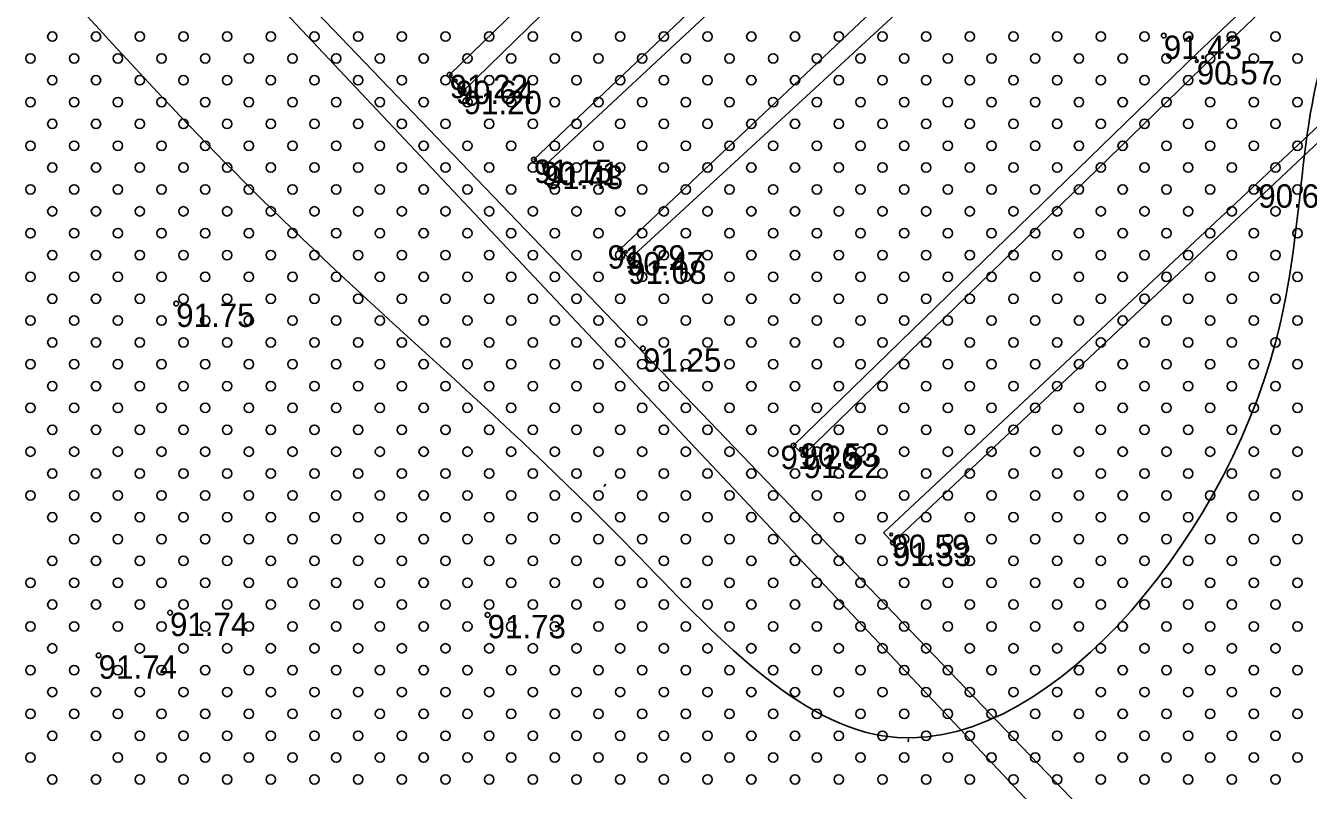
# Model space of a CAD drawing. Extents: x 316000 to 728450, y 314368 to 726000.
# Drawn here: x 725766.2 to 725971.8, y 315036.8 to 315159.2 of the extents above; entities that cross this region are included whole.
import ezdxf

# ---------------------------------------------------------------- set-up
doc = ezdxf.new("R2010")
doc.units = 0
for name, color, linetype in [('HIDG_ELEM_####_####_#', 7, 'Continuous'), ('HIDG_GRAV_####_####_#', 7, 'Continuous'), ('RELJ_AATZ_####_TKST_#', 7, 'Continuous'), ('RELJ_ELEM_####_####_#', 7, 'Continuous'), ('RELJ_HORZ_PAMT_####_#', 7, 'Continuous'), ('RELJ_NOGA_####_####_#', 7, 'Continuous'), ('TERT_ELEM_####_####_#', 7, 'Continuous'), ('TERT_KONT_####_####_#', 7, 'Continuous')]:
    doc.layers.add(name, color=color, linetype=linetype)

msp = doc.modelspace()

# ---------------------------------------------------------------- linework, layer by layer
at = {"layer": 'HIDG_ELEM_####_####_#'}
for centre in [(725953.87, 315153.57), (725835.14, 315150.43), (725848.81, 315137.44), (725963.77, 315133.08), (725862.38, 315123), (725890.5, 315091.43), (725904.91, 315077.72)]:
    msp.add_circle(centre, 0.225, dxfattribs=at)
at = {"layer": 'HIDG_GRAV_####_####_#'}
for points in [[(725550.64, 315437.37), (725654.91, 315324.09), (725793.17, 315176.93), (726030.02, 314925.45), (726035.1, 314929.94), (725796.17, 315178.83)], [(726013.86, 315323.76), (726014.55, 315322.37), (725916.94, 315227.27), (725836.4, 315148.81), (725834.15, 315151.37), (725916.39, 315231.21), (726013.86, 315323.76)], [(726026.72, 315310.03), (726028.38, 315308.12), (725929.27, 315211.22), (725849.42, 315136.82), (725847.67, 315137.8), (725927.82, 315213.86), (726026.72, 315310.03)], [(726041.22, 315294.28), (726042.74, 315292.12), (725933.2, 315186.57), (725862.99, 315121.84), (725861.5, 315123.44), (725931.43, 315189.54), (726041.22, 315294.28)], [(726067.39, 315262.47), (726068.58, 315261.15), (725954.8, 315152.62), (725890.85, 315090.51), (725889.28, 315091.99), (725953.78, 315154.65), (726067.39, 315262.47)], [(726082.26, 315247.75), (726083.77, 315246.23), (726040.2, 315203.48), (725905.19, 315076.43), (725903.68, 315078.01), (726039.2, 315204.79), (726082.26, 315247.75)]]:
    msp.add_lwpolyline(points, dxfattribs=at)
at = {"layer": 'RELJ_ELEM_####_####_#'}
for centre in [(725948.58, 315157.65), (725834.15, 315151.37), (725836.4, 315148.81), (725847.67, 315137.8), (725849.42, 315136.82), (725861.5, 315123.44), (725862.99, 315121.84), (725790.35, 315114.73), (725865.14, 315107.54), (725889.28, 315091.99), (725890.85, 315090.51), (725905.19, 315076.43), (725789.36, 315065.21), (725840.24, 315064.86), (725777.92, 315058.37)]:
    msp.add_circle(centre, 0.375, dxfattribs=at)
at = {"layer": 'RELJ_HORZ_PAMT_####_#'}
for p, q in [((725859.18, 315085.78), (725858.85, 315085.4)), ((725907.67, 315045.01), (725907.62, 315044.51))]:
    msp.add_line(p, q, dxfattribs=at)
for points in [[(726116.34, 315699.09), (726105.94, 315702.69), (726040.13, 315715), (725990.82, 315710.42), (725942.03, 315708.25), (725920.28, 315706.77), (725880.37, 315714.51), (725859.05, 315708.68), (725859.05, 315672.66), (725851.26, 315613.97), (725853.47, 315568.9), (725841, 315555.79), (725885.56, 315509.63), (725935.94, 315461.49), (725983.42, 315406.25), (726032.86, 315360.51), (726082.85, 315311.19), (726122.23, 315248.76), (726137.05, 315229.29), (726180.19, 315183.1), (726194.52, 315168.27), (726211.91, 315146.93), (726212.51, 315143.16)], [(726081.57, 315247.05), (726057.5, 315241.5), (726036.5, 315213.5), (725977, 315161), (725966.5, 315108.5), (725903.5, 315045.5), (725862.12, 315076.6), (725805.5, 315130), (725759.7, 315178.88), (725709.89, 315228.8), (725646.99, 315287.19), (725634.68, 315314.96), (725629.04, 315327.48), (725557.35, 315340.26), (725478.3, 315344.16)]]:
    msp.add_spline(points, degree=3, dxfattribs=at)
at = {"layer": 'RELJ_NOGA_####_####_#'}
for points in [[(726259.12, 315084.51), (726262.72, 315089.26), (726261.56, 315090.84), (726260.2, 315092.42), (726257.29, 315095.53), (726218.91, 315136.38), (726180.31, 315176.84), (726128.67, 315229.97), (726063.7, 315298.11), (725999.9, 315366.09), (725937.21, 315432.09), (725876.35, 315495.23), (725810.58, 315563.08), (725744.7, 315632.91)], [(725740.86, 315626.98), (725805.54, 315558.12), (725870.39, 315491.15), (725932.8, 315426.8), (725994.98, 315360.84), (726059.66, 315292.12), (726075.75, 315275.46), (726092.08, 315259.04), (726108.47, 315242.67), (726124.69, 315226.14), (726193.27, 315154.03), (726250.06, 315092.6), (726256.32, 315085.83), (726258.82, 315084.29), (726259.12, 315084.51)]]:
    msp.add_spline(points, degree=3, dxfattribs=at)
at = {"layer": 'TERT_ELEM_####_####_#'}
for centre in [(725770.5, 315157.5), (725777.5, 315157.5), (725784.5, 315157.5), (725791.5, 315157.5), (725798.5, 315157.5), (725805.5, 315157.5), (725812.5, 315157.5), (725819.5, 315157.5), (725826.5, 315157.5), (725833.5, 315157.5), (725840.5, 315157.5), (725847.5, 315157.5), (725854.5, 315157.5), (725861.5, 315157.5), (725868.5, 315157.5), (725875.5, 315157.5), (725882.5, 315157.5), (725889.5, 315157.5), (725896.5, 315157.5), (725903.5, 315157.5), (725910.5, 315157.5), (725917.5, 315157.5), (725924.5, 315157.5), (725931.5, 315157.5), (725938.5, 315157.5), (725945.5, 315157.5), (725952.5, 315157.5), (725959.5, 315157.5), (725966.5, 315157.5), (725767, 315154), (725774, 315154), (725781, 315154), (725788, 315154), (725795, 315154), (725802, 315154), (725809, 315154), (725816, 315154), (725823, 315154), (725830, 315154), (725837, 315154), (725844, 315154), (725851, 315154), (725858, 315154), (725865, 315154), (725872, 315154), (725879, 315154), (725886, 315154), (725893, 315154), (725900, 315154), (725907, 315154), (725914, 315154), (725921, 315154), (725928, 315154), (725935, 315154), (725942, 315154), (725949, 315154), (725956, 315154), (725963, 315154), (725970, 315154), (725770.5, 315150.5), (725777.5, 315150.5), (725784.5, 315150.5), (725791.5, 315150.5), (725798.5, 315150.5), (725805.5, 315150.5), (725812.5, 315150.5), (725819.5, 315150.5), (725826.5, 315150.5), (725833.5, 315150.5), (725840.5, 315150.5), (725847.5, 315150.5), (725854.5, 315150.5), (725861.5, 315150.5), (725868.5, 315150.5), (725875.5, 315150.5), (725882.5, 315150.5), (725889.5, 315150.5), (725896.5, 315150.5), (725903.5, 315150.5), (725910.5, 315150.5), (725917.5, 315150.5), (725924.5, 315150.5), (725931.5, 315150.5), (725938.5, 315150.5), (725945.5, 315150.5), (725952.5, 315150.5), (725959.5, 315150.5), (725966.5, 315150.5), (725767, 315147), (725774, 315147), (725781, 315147), (725788, 315147), (725795, 315147), (725802, 315147), (725809, 315147), (725816, 315147), (725823, 315147), (725830, 315147), (725837, 315147), (725844, 315147), (725851, 315147), (725858, 315147), (725865, 315147), (725872, 315147), (725879, 315147), (725886, 315147), (725893, 315147), (725900, 315147), (725907, 315147), (725914, 315147), (725921, 315147), (725928, 315147), (725935, 315147), (725942, 315147), (725949, 315147), (725956, 315147), (725963, 315147), (725970, 315147), (725770.5, 315143.5), (725777.5, 315143.5), (725784.5, 315143.5), (725791.5, 315143.5), (725798.5, 315143.5), (725805.5, 315143.5), (725812.5, 315143.5), (725819.5, 315143.5), (725826.5, 315143.5), (725833.5, 315143.5), (725840.5, 315143.5), (725847.5, 315143.5), (725854.5, 315143.5), (725861.5, 315143.5), (725868.5, 315143.5), (725875.5, 315143.5), (725882.5, 315143.5), (725889.5, 315143.5), (725896.5, 315143.5), (725903.5, 315143.5), (725910.5, 315143.5), (725917.5, 315143.5), (725924.5, 315143.5), (725931.5, 315143.5), (725938.5, 315143.5), (725945.5, 315143.5), (725952.5, 315143.5), (725959.5, 315143.5), (725966.5, 315143.5), (725767, 315140), (725774, 315140), (725781, 315140), (725788, 315140), (725795, 315140), (725802, 315140), (725809, 315140), (725816, 315140), (725823, 315140), (725830, 315140), (725837, 315140), (725844, 315140), (725851, 315140), (725858, 315140), (725865, 315140), (725872, 315140), (725879, 315140), (725886, 315140), (725893, 315140), (725900, 315140), (725907, 315140), (725914, 315140), (725921, 315140), (725928, 315140), (725935, 315140), (725942, 315140), (725949, 315140), (725956, 315140), (725963, 315140), (725970, 315140), (725770.5, 315136.5), (725777.5, 315136.5), (725784.5, 315136.5), (725791.5, 315136.5), (725798.5, 315136.5), (725805.5, 315136.5), (725812.5, 315136.5), (725819.5, 315136.5), (725826.5, 315136.5), (725833.5, 315136.5), (725840.5, 315136.5), (725847.5, 315136.5), (725854.5, 315136.5), (725861.5, 315136.5), (725868.5, 315136.5), (725875.5, 315136.5), (725882.5, 315136.5), (725889.5, 315136.5), (725896.5, 315136.5), (725903.5, 315136.5), (725910.5, 315136.5), (725917.5, 315136.5), (725924.5, 315136.5), (725931.5, 315136.5), (725938.5, 315136.5), (725945.5, 315136.5), (725952.5, 315136.5), (725959.5, 315136.5), (725966.5, 315136.5), (725767, 315133), (725774, 315133), (725781, 315133), (725788, 315133), (725795, 315133), (725802, 315133), (725809, 315133), (725816, 315133), (725823, 315133), (725830, 315133), (725837, 315133), (725844, 315133), (725851, 315133), (725858, 315133), (725865, 315133), (725872, 315133), (725879, 315133), (725886, 315133), (725893, 315133), (725900, 315133), (725907, 315133), (725914, 315133), (725921, 315133), (725928, 315133), (725935, 315133), (725942, 315133), (725949, 315133), (725956, 315133), (725963, 315133), (725970, 315133), (725770.5, 315129.5), (725777.5, 315129.5), (725784.5, 315129.5), (725791.5, 315129.5), (725798.5, 315129.5), (725805.5, 315129.5), (725812.5, 315129.5), (725819.5, 315129.5), (725826.5, 315129.5), (725833.5, 315129.5), (725840.5, 315129.5), (725847.5, 315129.5), (725854.5, 315129.5), (725861.5, 315129.5), (725868.5, 315129.5), (725875.5, 315129.5), (725882.5, 315129.5), (725889.5, 315129.5), (725896.5, 315129.5), (725903.5, 315129.5), (725910.5, 315129.5), (725917.5, 315129.5), (725924.5, 315129.5), (725931.5, 315129.5), (725938.5, 315129.5), (725945.5, 315129.5), (725952.5, 315129.5), (725959.5, 315129.5), (725966.5, 315129.5), (725767, 315126), (725774, 315126), (725781, 315126), (725788, 315126), (725795, 315126), (725802, 315126), (725809, 315126), (725816, 315126), (725823, 315126), (725830, 315126), (725837, 315126), (725844, 315126), (725851, 315126), (725858, 315126), (725865, 315126), (725872, 315126), (725879, 315126), (725886, 315126), (725893, 315126), (725900, 315126), (725907, 315126), (725914, 315126), (725921, 315126), (725928, 315126), (725935, 315126), (725942, 315126), (725949, 315126), (725956, 315126), (725963, 315126), (725970, 315126), (725770.5, 315122.5), (725777.5, 315122.5), (725784.5, 315122.5), (725791.5, 315122.5), (725798.5, 315122.5), (725805.5, 315122.5), (725812.5, 315122.5), (725819.5, 315122.5), (725826.5, 315122.5), (725833.5, 315122.5), (725840.5, 315122.5), (725847.5, 315122.5), (725854.5, 315122.5), (725861.5, 315122.5), (725868.5, 315122.5), (725875.5, 315122.5), (725882.5, 315122.5), (725889.5, 315122.5), (725896.5, 315122.5), (725903.5, 315122.5), (725910.5, 315122.5), (725917.5, 315122.5), (725924.5, 315122.5), (725931.5, 315122.5), (725938.5, 315122.5), (725945.5, 315122.5), (725952.5, 315122.5), (725959.5, 315122.5), (725966.5, 315122.5), (725767, 315119), (725774, 315119), (725781, 315119), (725788, 315119), (725795, 315119), (725802, 315119), (725809, 315119), (725816, 315119), (725823, 315119), (725830, 315119), (725837, 315119), (725844, 315119), (725851, 315119), (725858, 315119), (725865, 315119), (725872, 315119), (725879, 315119), (725886, 315119), (725893, 315119), (725900, 315119), (725907, 315119), (725914, 315119), (725921, 315119), (725928, 315119), (725935, 315119), (725942, 315119), (725949, 315119), (725956, 315119), (725963, 315119), (725970, 315119), (725770.5, 315115.5), (725777.5, 315115.5), (725784.5, 315115.5), (725791.5, 315115.5), (725798.5, 315115.5), (725805.5, 315115.5), (725812.5, 315115.5), (725819.5, 315115.5), (725826.5, 315115.5), (725833.5, 315115.5), (725840.5, 315115.5), (725847.5, 315115.5), (725854.5, 315115.5), (725861.5, 315115.5), (725868.5, 315115.5), (725875.5, 315115.5), (725882.5, 315115.5), (725889.5, 315115.5), (725896.5, 315115.5), (725903.5, 315115.5), (725910.5, 315115.5), (725917.5, 315115.5), (725924.5, 315115.5), (725931.5, 315115.5), (725938.5, 315115.5), (725945.5, 315115.5), (725952.5, 315115.5), (725959.5, 315115.5), (725966.5, 315115.5), (725767, 315112), (725774, 315112), (725781, 315112), (725788, 315112), (725795, 315112), (725802, 315112), (725809, 315112), (725816, 315112), (725823, 315112), (725830, 315112), (725837, 315112), (725844, 315112), (725851, 315112), (725858, 315112), (725865, 315112), (725872, 315112), (725879, 315112), (725886, 315112), (725893, 315112), (725900, 315112), (725907, 315112), (725914, 315112), (725921, 315112), (725928, 315112), (725935, 315112), (725942, 315112), (725949, 315112), (725956, 315112), (725963, 315112), (725970, 315112), (725770.5, 315108.5), (725777.5, 315108.5), (725784.5, 315108.5), (725791.5, 315108.5), (725798.5, 315108.5), (725805.5, 315108.5), (725812.5, 315108.5), (725819.5, 315108.5), (725826.5, 315108.5), (725833.5, 315108.5), (725840.5, 315108.5), (725847.5, 315108.5), (725854.5, 315108.5), (725861.5, 315108.5), (725868.5, 315108.5), (725875.5, 315108.5), (725882.5, 315108.5), (725889.5, 315108.5), (725896.5, 315108.5), (725903.5, 315108.5), (725910.5, 315108.5), (725917.5, 315108.5), (725924.5, 315108.5), (725931.5, 315108.5), (725938.5, 315108.5), (725945.5, 315108.5), (725952.5, 315108.5), (725959.5, 315108.5), (725966.5, 315108.5), (725767, 315105), (725774, 315105), (725781, 315105), (725788, 315105), (725795, 315105), (725802, 315105), (725809, 315105), (725816, 315105), (725823, 315105), (725830, 315105), (725837, 315105), (725844, 315105), (725851, 315105), (725858, 315105), (725865, 315105), (725872, 315105), (725879, 315105), (725886, 315105), (725893, 315105), (725900, 315105), (725907, 315105), (725914, 315105), (725921, 315105), (725928, 315105), (725935, 315105), (725942, 315105), (725949, 315105), (725956, 315105), (725963, 315105), (725970, 315105), (725770.5, 315101.5), (725777.5, 315101.5), (725784.5, 315101.5), (725791.5, 315101.5), (725798.5, 315101.5), (725805.5, 315101.5), (725812.5, 315101.5), (725819.5, 315101.5), (725826.5, 315101.5), (725833.5, 315101.5), (725840.5, 315101.5), (725847.5, 315101.5), (725854.5, 315101.5), (725861.5, 315101.5), (725868.5, 315101.5), (725875.5, 315101.5), (725882.5, 315101.5), (725889.5, 315101.5), (725896.5, 315101.5), (725903.5, 315101.5), (725910.5, 315101.5), (725917.5, 315101.5), (725924.5, 315101.5), (725931.5, 315101.5), (725938.5, 315101.5), (725945.5, 315101.5), (725952.5, 315101.5), (725959.5, 315101.5), (725966.5, 315101.5), (725767, 315098), (725774, 315098), (725781, 315098), (725788, 315098), (725795, 315098), (725802, 315098), (725809, 315098), (725816, 315098), (725823, 315098), (725830, 315098), (725837, 315098), (725844, 315098), (725851, 315098), (725858, 315098), (725865, 315098), (725872, 315098), (725879, 315098), (725886, 315098), (725893, 315098), (725900, 315098), (725907, 315098), (725914, 315098), (725921, 315098), (725928, 315098), (725935, 315098), (725942, 315098), (725949, 315098), (725956, 315098), (725963, 315098), (725970, 315098), (725770.5, 315094.5), (725777.5, 315094.5), (725784.5, 315094.5), (725791.5, 315094.5), (725798.5, 315094.5), (725805.5, 315094.5), (725812.5, 315094.5), (725819.5, 315094.5), (725826.5, 315094.5), (725833.5, 315094.5), (725840.5, 315094.5), (725847.5, 315094.5), (725854.5, 315094.5), (725861.5, 315094.5), (725868.5, 315094.5), (725875.5, 315094.5), (725882.5, 315094.5), (725889.5, 315094.5), (725896.5, 315094.5), (725903.5, 315094.5), (725910.5, 315094.5), (725917.5, 315094.5), (725924.5, 315094.5), (725931.5, 315094.5), (725938.5, 315094.5), (725945.5, 315094.5), (725952.5, 315094.5), (725959.5, 315094.5), (725966.5, 315094.5), (725767, 315091), (725774, 315091), (725781, 315091), (725788, 315091), (725795, 315091), (725802, 315091), (725809, 315091), (725816, 315091), (725823, 315091), (725830, 315091), (725837, 315091), (725844, 315091), (725851, 315091), (725858, 315091), (725865, 315091), (725872, 315091), (725879, 315091), (725886, 315091), (725893, 315091), (725900, 315091), (725907, 315091), (725914, 315091), (725921, 315091), (725928, 315091), (725935, 315091), (725942, 315091), (725949, 315091), (725956, 315091), (725963, 315091), (725970, 315091), (725770.5, 315087.5), (725777.5, 315087.5), (725784.5, 315087.5), (725791.5, 315087.5), (725798.5, 315087.5), (725805.5, 315087.5), (725812.5, 315087.5), (725819.5, 315087.5), (725826.5, 315087.5), (725833.5, 315087.5), (725840.5, 315087.5), (725847.5, 315087.5), (725854.5, 315087.5), (725861.5, 315087.5), (725868.5, 315087.5), (725875.5, 315087.5), (725882.5, 315087.5), (725889.5, 315087.5), (725896.5, 315087.5), (725903.5, 315087.5), (725910.5, 315087.5), (725917.5, 315087.5), (725924.5, 315087.5), (725931.5, 315087.5), (725938.5, 315087.5), (725945.5, 315087.5), (725952.5, 315087.5), (725959.5, 315087.5), (725966.5, 315087.5), (725767, 315084), (725774, 315084), (725781, 315084), (725788, 315084), (725795, 315084), (725802, 315084), (725809, 315084), (725816, 315084), (725823, 315084), (725830, 315084), (725837, 315084), (725844, 315084), (725851, 315084), (725858, 315084), (725865, 315084), (725872, 315084), (725879, 315084), (725886, 315084), (725893, 315084), (725900, 315084), (725907, 315084), (725914, 315084), (725921, 315084), (725928, 315084), (725935, 315084), (725942, 315084), (725949, 315084), (725956, 315084), (725963, 315084), (725970, 315084), (725770.5, 315080.5), (725777.5, 315080.5), (725784.5, 315080.5), (725791.5, 315080.5), (725798.5, 315080.5), (725805.5, 315080.5), (725812.5, 315080.5), (725819.5, 315080.5), (725826.5, 315080.5), (725833.5, 315080.5), (725840.5, 315080.5), (725847.5, 315080.5), (725854.5, 315080.5), (725861.5, 315080.5), (725868.5, 315080.5), (725875.5, 315080.5), (725882.5, 315080.5), (725889.5, 315080.5), (725896.5, 315080.5), (725903.5, 315080.5), (725910.5, 315080.5), (725917.5, 315080.5), (725924.5, 315080.5), (725931.5, 315080.5), (725938.5, 315080.5), (725945.5, 315080.5), (725952.5, 315080.5), (725959.5, 315080.5), (725966.5, 315080.5), (725774, 315077), (725781, 315077), (725788, 315077), (725795, 315077), (725802, 315077), (725809, 315077), (725816, 315077), (725823, 315077), (725830, 315077), (725837, 315077), (725844, 315077), (725851, 315077), (725858, 315077), (725865, 315077), (725872, 315077), (725879, 315077), (725886, 315077), (725893, 315077), (725900, 315077), (725907, 315077), (725914, 315077), (725921, 315077), (725928, 315077), (725935, 315077), (725942, 315077), (725949, 315077), (725956, 315077), (725963, 315077), (725970, 315077), (725770.5, 315073.5), (725777.5, 315073.5), (725784.5, 315073.5), (725791.5, 315073.5), (725798.5, 315073.5), (725805.5, 315073.5), (725812.5, 315073.5), (725819.5, 315073.5), (725826.5, 315073.5), (725833.5, 315073.5), (725840.5, 315073.5), (725847.5, 315073.5), (725854.5, 315073.5), (725861.5, 315073.5), (725868.5, 315073.5), (725875.5, 315073.5), (725882.5, 315073.5), (725889.5, 315073.5), (725896.5, 315073.5), (725903.5, 315073.5), (725910.5, 315073.5), (725917.5, 315073.5), (725924.5, 315073.5), (725931.5, 315073.5), (725938.5, 315073.5), (725945.5, 315073.5), (725952.5, 315073.5), (725959.5, 315073.5), (725966.5, 315073.5), (725767, 315070), (725774, 315070), (725781, 315070), (725788, 315070), (725795, 315070), (725802, 315070), (725809, 315070), (725816, 315070), (725823, 315070), (725830, 315070), (725837, 315070), (725844, 315070), (725851, 315070), (725858, 315070), (725865, 315070), (725872, 315070), (725879, 315070), (725886, 315070), (725893, 315070), (725900, 315070), (725907, 315070), (725914, 315070), (725921, 315070), (725928, 315070), (725935, 315070), (725942, 315070), (725949, 315070), (725956, 315070), (725963, 315070), (725970, 315070), (725770.5, 315066.5), (725777.5, 315066.5), (725784.5, 315066.5), (725791.5, 315066.5), (725798.5, 315066.5), (725805.5, 315066.5), (725812.5, 315066.5), (725819.5, 315066.5), (725826.5, 315066.5), (725833.5, 315066.5), (725840.5, 315066.5), (725847.5, 315066.5), (725854.5, 315066.5), (725861.5, 315066.5), (725868.5, 315066.5), (725875.5, 315066.5), (725882.5, 315066.5), (725889.5, 315066.5), (725896.5, 315066.5), (725903.5, 315066.5), (725910.5, 315066.5), (725917.5, 315066.5), (725924.5, 315066.5), (725931.5, 315066.5), (725938.5, 315066.5), (725945.5, 315066.5), (725952.5, 315066.5), (725959.5, 315066.5), (725966.5, 315066.5), (725767, 315063), (725774, 315063), (725781, 315063), (725788, 315063), (725795, 315063), (725802, 315063), (725809, 315063), (725816, 315063), (725823, 315063), (725830, 315063), (725837, 315063), (725844, 315063), (725851, 315063), (725858, 315063), (725865, 315063), (725872, 315063), (725879, 315063), (725886, 315063), (725893, 315063), (725900, 315063), (725907, 315063), (725914, 315063), (725921, 315063), (725928, 315063), (725935, 315063), (725942, 315063), (725949, 315063), (725956, 315063), (725963, 315063), (725970, 315063), (725770.5, 315059.5), (725784.5, 315059.5), (725791.5, 315059.5), (725798.5, 315059.5), (725805.5, 315059.5), (725812.5, 315059.5), (725819.5, 315059.5), (725826.5, 315059.5), (725833.5, 315059.5), (725840.5, 315059.5), (725847.5, 315059.5), (725854.5, 315059.5), (725861.5, 315059.5), (725868.5, 315059.5), (725875.5, 315059.5), (725882.5, 315059.5), (725889.5, 315059.5), (725896.5, 315059.5), (725903.5, 315059.5), (725910.5, 315059.5), (725917.5, 315059.5), (725924.5, 315059.5), (725931.5, 315059.5), (725938.5, 315059.5), (725945.5, 315059.5), (725952.5, 315059.5), (725959.5, 315059.5), (725966.5, 315059.5), (725767, 315056), (725774, 315056), (725781, 315056), (725788, 315056), (725795, 315056), (725802, 315056), (725809, 315056), (725816, 315056), (725823, 315056), (725830, 315056), (725837, 315056), (725844, 315056), (725851, 315056), (725858, 315056), (725865, 315056), (725872, 315056), (725879, 315056), (725886, 315056), (725893, 315056), (725900, 315056), (725907, 315056), (725914, 315056), (725921, 315056), (725928, 315056), (725935, 315056), (725942, 315056), (725949, 315056), (725956, 315056), (725963, 315056), (725970, 315056), (725770.5, 315052.5), (725777.5, 315052.5), (725784.5, 315052.5), (725791.5, 315052.5), (725798.5, 315052.5), (725805.5, 315052.5), (725812.5, 315052.5), (725819.5, 315052.5), (725826.5, 315052.5), (725833.5, 315052.5), (725840.5, 315052.5), (725847.5, 315052.5), (725854.5, 315052.5), (725861.5, 315052.5), (725868.5, 315052.5), (725875.5, 315052.5), (725882.5, 315052.5), (725889.5, 315052.5), (725896.5, 315052.5), (725903.5, 315052.5), (725910.5, 315052.5), (725917.5, 315052.5), (725924.5, 315052.5), (725931.5, 315052.5), (725938.5, 315052.5), (725945.5, 315052.5), (725952.5, 315052.5), (725959.5, 315052.5), (725966.5, 315052.5), (725767, 315049), (725774, 315049), (725781, 315049), (725788, 315049), (725795, 315049), (725802, 315049), (725809, 315049), (725816, 315049), (725823, 315049), (725830, 315049), (725837, 315049), (725844, 315049), (725851, 315049), (725858, 315049), (725865, 315049), (725872, 315049), (725879, 315049), (725886, 315049), (725893, 315049), (725900, 315049), (725907, 315049), (725914, 315049), (725921, 315049), (725928, 315049), (725935, 315049), (725942, 315049), (725949, 315049), (725956, 315049), (725963, 315049), (725970, 315049), (725770.5, 315045.5), (725777.5, 315045.5), (725784.5, 315045.5), (725791.5, 315045.5), (725798.5, 315045.5), (725805.5, 315045.5), (725812.5, 315045.5), (725819.5, 315045.5), (725826.5, 315045.5), (725833.5, 315045.5), (725840.5, 315045.5), (725847.5, 315045.5), (725854.5, 315045.5), (725861.5, 315045.5), (725868.5, 315045.5), (725875.5, 315045.5), (725882.5, 315045.5), (725889.5, 315045.5), (725896.5, 315045.5), (725903.5, 315045.5), (725910.5, 315045.5), (725917.5, 315045.5), (725924.5, 315045.5), (725931.5, 315045.5), (725938.5, 315045.5), (725945.5, 315045.5), (725952.5, 315045.5), (725959.5, 315045.5), (725966.5, 315045.5), (725767, 315042), (725781, 315042), (725788, 315042), (725795, 315042), (725802, 315042), (725809, 315042), (725816, 315042), (725823, 315042), (725830, 315042), (725837, 315042), (725844, 315042), (725851, 315042), (725858, 315042), (725865, 315042), (725872, 315042), (725879, 315042), (725886, 315042), (725893, 315042), (725900, 315042), (725907, 315042), (725914, 315042), (725921, 315042), (725928, 315042), (725935, 315042), (725942, 315042), (725949, 315042), (725956, 315042), (725963, 315042), (725970, 315042), (725770.5, 315038.5), (725777.5, 315038.5), (725784.5, 315038.5), (725791.5, 315038.5), (725798.5, 315038.5), (725805.5, 315038.5), (725812.5, 315038.5), (725819.5, 315038.5), (725826.5, 315038.5), (725833.5, 315038.5), (725840.5, 315038.5), (725847.5, 315038.5), (725854.5, 315038.5), (725861.5, 315038.5), (725868.5, 315038.5), (725875.5, 315038.5), (725882.5, 315038.5), (725889.5, 315038.5), (725896.5, 315038.5), (725903.5, 315038.5), (725910.5, 315038.5), (725917.5, 315038.5), (725924.5, 315038.5), (725931.5, 315038.5), (725938.5, 315038.5), (725945.5, 315038.5), (725952.5, 315038.5), (725959.5, 315038.5), (725966.5, 315038.5)]:
    msp.add_circle(centre, 0.75, dxfattribs=at)
at = {"layer": 'TERT_KONT_####_####_#'}
msp.add_spline([(726171.05, 315177.78), (726060.22, 315058.34), (726046.85, 314926.57), (725966, 314840.49), (725918.95, 314808.85), (725841.04, 314808.85), (725695.46, 314898.17)], degree=3, dxfattribs=at)

# ---------------------------------------------------------------- texts
at = {"layer": 'RELJ_AATZ_####_TKST_#'}
for s, p in [('91.43', (725948.58, 315153.9)), ('90.57', (725953.87, 315149.82)), ('91.22', (725834.15, 315147.62)), ('90.64', (725835.14, 315146.68)), ('91.20', (725836.4, 315145.06)), ('91.15', (725847.67, 315134.05)), ('90.71', (725848.81, 315133.69)), ('91.43', (725849.42, 315133.07)), ('90.64', (725963.73, 315130.08)), ('91.29', (725859.45, 315120.32)), ('90.47', (725862.41, 315119.24)), ('91.08', (725862.76, 315117.88)), ('91.75', (725790.35, 315110.98)), ('91.25', (725865.14, 315103.79)), ('91.26', (725887.16, 315088.22)), ('90.53', (725890.37, 315088.59)), ('91.22', (725890.85, 315086.76)), ('90.59', (725904.91, 315073.97)), ('91.33', (725905.19, 315072.68)), ('91.74', (725789.36, 315061.46)), ('91.73', (725840.24, 315061.11)), ('91.74', (725777.92, 315054.62))]:
    msp.add_text(s, height=3.75, dxfattribs=at).set_placement(p)

doc.saveas('drawing.dxf')
